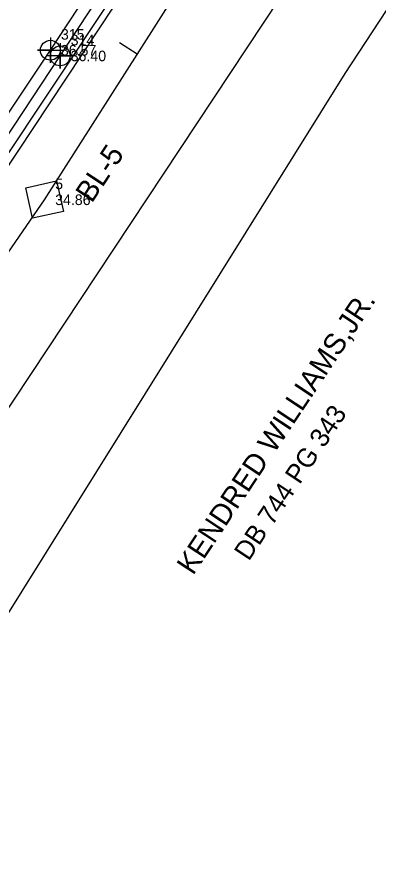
# Model space of a CAD drawing. Extents: x 2603627 to 2605187, y 896619 to 899063.
# Drawn here: x 2604787 to 2604872.4, y 898327.7 to 898527.2 of the extents above; entities that cross this region are included whole.
import ezdxf

# ---------------------------------------------------------------- set-up
doc = ezdxf.new("R2010")
doc.units = 0
for name, color, linetype in [('CTL Supplemental Horizontal and Vertical CELL', 7, 'Continuous'), ('CTL Supplemental Horizontal and Vertical Cogo Elevation', 7, 'Continuous'), ('CTL Supplemental Horizontal and Vertical Cogo Number', 7, 'Continuous'), ('CTL Supplemental Horizontal and Vertical Text', 7, 'Continuous'), ('Exist Horizontal Baseline Alignment', 7, 'Continuous'), ('Exist Horizontal Baseline Alignment Tick small', 7, 'Continuous'), ('Exist Property Deed Book Text', 7, 'Continuous'), ('Exist Property Owner Text', 7, 'Continuous'), ('Exist Right of Way Line', 7, 'Continuous'), ('Exist Roads EOP', 7, 'Continuous'), ('Exist Roads EOP Cogo Elevation', 7, 'Continuous'), ('Exist Roads EOP Cogo Number', 7, 'Continuous'), ('Exist Roads EOP Cogo Point CELL', 7, 'Continuous'), ('Exist Roads EOT', 7, 'Continuous'), ('Exist Roads EOT Cogo Elevation', 7, 'Continuous'), ('Exist Roads EOT Cogo Number', 7, 'Continuous'), ('Exist Roads EOT Cogo Point CELL', 7, 'Continuous'), ('Exist Utilities Telephone UG Cable SUE LOS C', 7, 'Continuous'), ('Exist Utilities Water UG Line SUE LOS B', 7, 'Continuous'), ('Exist Vegetation Woods Line', 7, 'Continuous')]:
    doc.layers.add(name, color=color, linetype=linetype)

# ---------------------------------------------------------------- blocks, each defined once
blk = doc.blocks.new('EXIST ROADS EOP COGO POINT')
at = {"layer": 'Exist Roads EOP Cogo Point CELL'}
blk.add_lwpolyline([(0, 0.06), (0, -0.06), (0, 0), (0.06, 0), (-0.06, 0)], dxfattribs=at)
blk.add_circle((0, 0), 0.0469, dxfattribs=at)
blk = doc.blocks.new('EXIST ROADS EOT COGO POINT')
at = {"layer": 'Exist Roads EOT Cogo Point CELL'}
blk.add_lwpolyline([(0, 0.06), (0, -0.06), (0, 0), (-0.06, 0), (0.06, 0)], dxfattribs=at)
blk.add_circle((0, 0), 0.0469, dxfattribs=at)
blk = doc.blocks.new('CTL SUPPLEMENTAL HORIZONTAL AND VERTICAL')
at = {"layer": 'CTL Supplemental Horizontal and Vertical CELL'}
blk.add_line((0, 0), (0, 0), dxfattribs=at)
blk.add_lwpolyline([(-0.1043, 0.0004), (0.0005, 0.1052), (0.1055, 0.0002), (0.0007, -0.1047)], close=True, dxfattribs=at)

msp = doc.modelspace()

# ---------------------------------------------------------------- linework, layer by layer
at = {"layer": 'Exist Horizontal Baseline Alignment'}
for p, q in [((2604793.6, 898483.9), (2605028.26, 898852.56)), ((2604544.96, 898124.44), (2604793.6, 898483.9))]:
    msp.add_line(p, q, dxfattribs=at)
at = {"layer": 'Exist Horizontal Baseline Alignment Tick small'}
msp.add_line((2604815.5, 898518.31), (2604811.28, 898520.99), dxfattribs=at)
at = {"layer": 'Exist Right of Way Line'}
msp.add_line((2604723.13, 898341.18), (2605082.79, 898884.13), dxfattribs=at)
at = {"layer": 'Exist Roads EOP'}
msp.add_lwpolyline([(2604713.86, 898392.44), (2604740.28, 898432.25), (2604768.45, 898474.26), (2604797.27, 898517.92), (2604823.93, 898558.47), (2604851.31, 898599.84), (2604878.52, 898641.09), (2604906.84, 898683.65), (2604934.68, 898725.71), (2604962.63, 898767.92), (2604989.32, 898808.49), (2605016.42, 898849.59), (2605045.34, 898893.33), (2605052.55, 898904.16)], dxfattribs=at)
at = {"layer": 'Exist Roads EOT'}
msp.add_lwpolyline([(2604598.04, 898223.4), (2604627.23, 898267.23), (2604654.64, 898308.57), (2604683.28, 898352.01), (2604711.27, 898394.14), (2604737.98, 898434.05), (2604766.04, 898475.94), (2604794.96, 898519.26), (2604821.61, 898559.82), (2604848.89, 898601.4), (2604876.12, 898642.73), (2604904.4, 898685.35), (2604932.33, 898727.23), (2604960.29, 898769.49), (2604987.32, 898810.19), (2605014.12, 898850.95), (2605043.08, 898894.89), (2605050.2, 898905.72)], dxfattribs=at)
at = {"layer": 'Exist Utilities Telephone UG Cable SUE LOS C'}
msp.add_line((2604753.32, 898447.21), (2604850.74, 898593.69), dxfattribs=at)
at = {"layer": 'Exist Utilities Water UG Line SUE LOS B'}
msp.add_lwpolyline([(2604590.41, 898183.07), (2604608.13, 898210.78), (2604631.33, 898247.72), (2604631.98, 898248.77), (2604637.93, 898260.9), (2604650.01, 898281.75), (2604670.13, 898312.66), (2604706.14, 898370.49), (2604744.2, 898428.79), (2604775.85, 898478.14), (2604817.62, 898541.22), (2604844.76, 898580.18), (2604876.2, 898627.22), (2604907.55, 898675.15), (2604931.69, 898711.47), (2604963.51, 898758.63), (2604991.08, 898800.9), (2605022.23, 898847.26), (2605044.13, 898880.13), (2605057.71, 898900.74)], dxfattribs=at)
at = {"layer": 'Exist Vegetation Woods Line'}
for points in [[(2604864.62, 898513.8), (2604942.25, 898632.13), (2604965.96, 898614.62)], [(2604653.24, 898142.95), (2604632.09, 898155.82), (2604674.87, 898231.68), (2604758.69, 898344.01), (2604864.62, 898513.8)]]:
    msp.add_lwpolyline(points, dxfattribs=at)

# ---------------------------------------------------------------- block references
at = {"layer": 'CTL Supplemental Horizontal and Vertical CELL', "xscale": 50, "yscale": 49.99999999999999, "rotation": 57.44453205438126}
msp.add_blockref('CTL SUPPLEMENTAL HORIZONTAL AND VERTICAL', (2604793.6, 898483.9), dxfattribs=at)
at = {"layer": 'Exist Roads EOP Cogo Point CELL', "xscale": 50, "yscale": 50}
msp.add_blockref('EXIST ROADS EOP COGO POINT', (2604797.27, 898517.92), dxfattribs=at)
at = {"layer": 'Exist Roads EOT Cogo Point CELL', "xscale": 50, "yscale": 50}
msp.add_blockref('EXIST ROADS EOT COGO POINT', (2604794.96, 898519.26), dxfattribs=at)

# ---------------------------------------------------------------- texts
at = {"layer": 'CTL Supplemental Horizontal and Vertical Cogo Elevation'}
msp.add_text('34.86', height=2.5, dxfattribs=at).set_placement((2604796.1, 898482.65))
at = {"layer": 'CTL Supplemental Horizontal and Vertical Cogo Number'}
msp.add_text('5', height=2.5, dxfattribs=at).set_placement((2604796.1, 898486.4))
at = {"layer": 'CTL Supplemental Horizontal and Vertical Text'}
msp.add_text('BL-5', height=5, rotation=56.4094, dxfattribs=at).set_placement((2604804.75, 898482.94))
at = {"layer": 'Exist Property Deed Book Text'}
msp.add_text('DB 744 PG 343', height=4.5, rotation=56.4133, dxfattribs=at).set_placement((2604841.85, 898398.28))
at = {"layer": 'Exist Property Owner Text'}
msp.add_text('KENDRED WILLIAMS,JR.', height=5, rotation=56.4133, dxfattribs=at).set_placement((2604828.69, 898394.91))
at = {"layer": 'Exist Roads EOP Cogo Elevation'}
msp.add_text('36.40', height=2.5, dxfattribs=at).set_placement((2604799.77, 898516.67))
at = {"layer": 'Exist Roads EOP Cogo Number'}
msp.add_text('314', height=2.5, dxfattribs=at).set_placement((2604799.77, 898520.42))
at = {"layer": 'Exist Roads EOT Cogo Elevation'}
msp.add_text('36.57', height=2.5, dxfattribs=at).set_placement((2604797.46, 898518.01))
at = {"layer": 'Exist Roads EOT Cogo Number'}
msp.add_text('315', height=2.5, dxfattribs=at).set_placement((2604797.46, 898521.76))

doc.saveas('drawing.dxf')
